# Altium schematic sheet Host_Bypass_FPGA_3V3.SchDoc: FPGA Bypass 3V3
size A4; Organization: Altium Limited.; Address1: Level 3, 12a Rodborough Rd; Address2: Frenchs Forest 2086; Address3: NSW; Address4: AUSTRALIA; DocumentNumber: 25; SheetNumber: 26; SheetTotal: 77; PageSetup: Record=PageOptions|CenterHorizontal=True|CenterVertical=True|PrintScale=0.97|XCorrection=1.00|YCorrection=1.00|PrintKind=0|BorderSize=5000000|LeftOffset=0|BottomOffset=0|Orientation=2|PaperLength=1000|PaperWidth=1000|Scale=100|PaperSource=7|PrintQuality=-4|MediaType=1|DitherType=10|PaperKind=A4 (210 x 297 mm)|PrintScaleMode=1
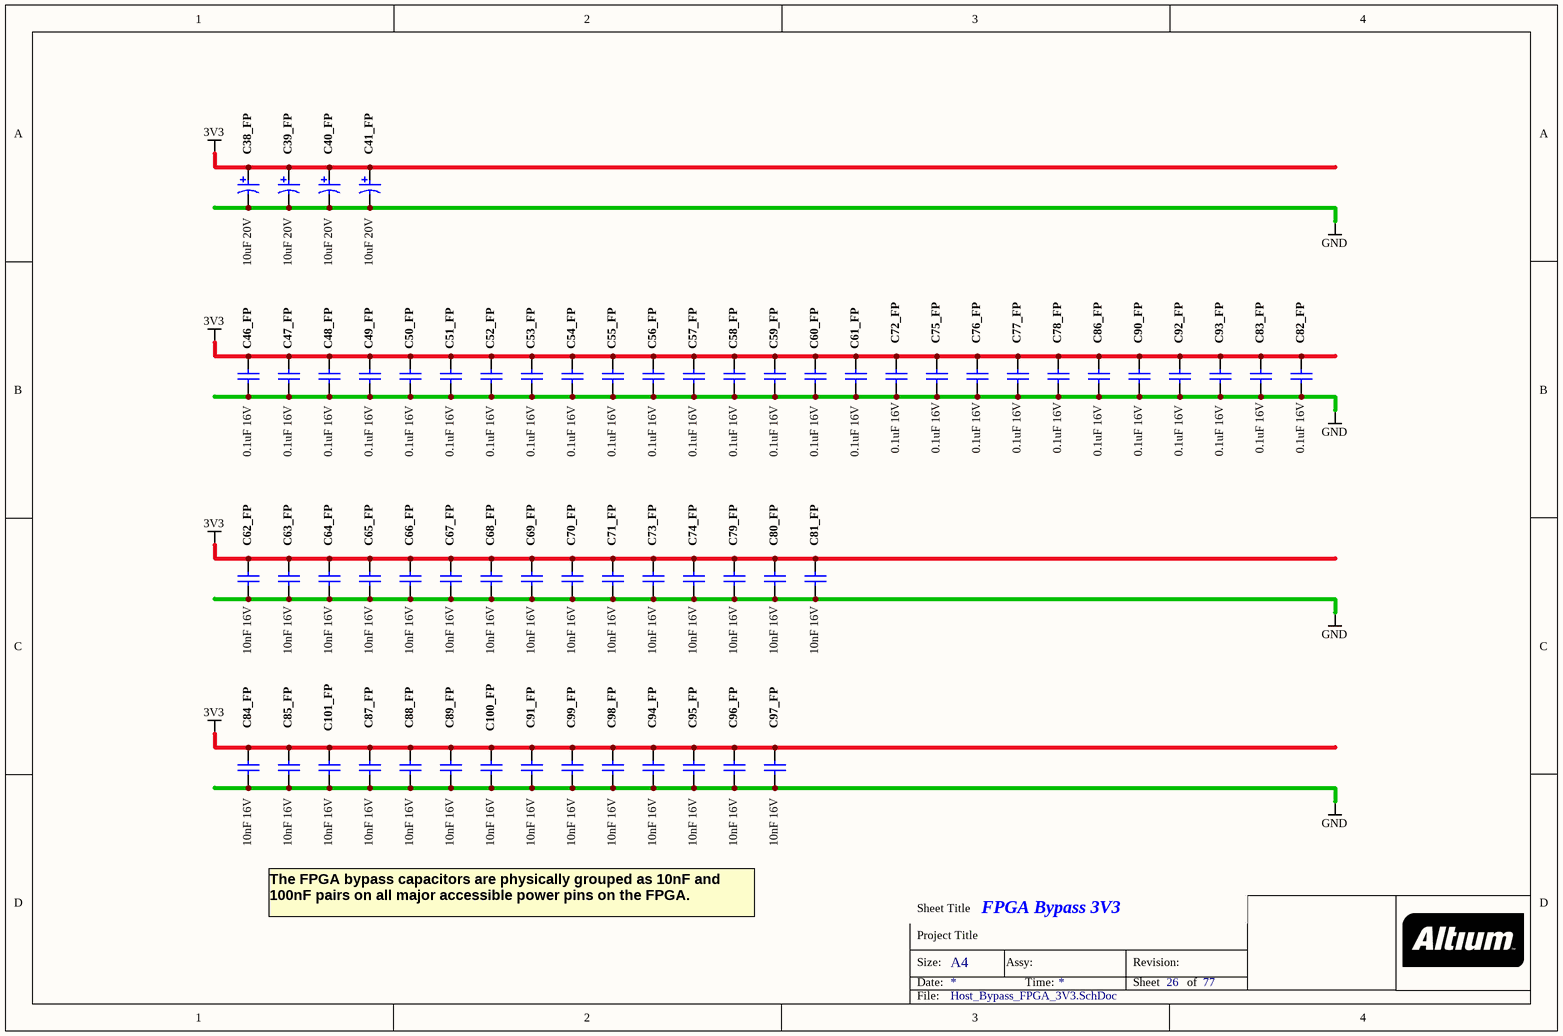
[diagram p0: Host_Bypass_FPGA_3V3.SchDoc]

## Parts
C38_FP  10uF 20V  [CAPC3528-STAR]
C39_FP  10uF 20V  [CAPC3528-STAR]
C40_FP  10uF 20V  [CAPC3528-STAR]
C41_FP  10uF 20V  [CAPC3528-STAR]
C46_FP  0.1uF 16V  [CAPC1005-STAR]
C47_FP  0.1uF 16V  [CAPC1005-STAR]
C48_FP  0.1uF 16V  [CAPC1005-STAR]
C49_FP  0.1uF 16V  [CAPC1005-STAR]
C50_FP  0.1uF 16V  [CAPC1005-STAR]
C51_FP  0.1uF 16V  [CAPC1005-STAR]
C52_FP  0.1uF 16V  [CAPC1005-STAR]
C53_FP  0.1uF 16V  [CAPC1005-STAR]
C54_FP  0.1uF 16V  [CAPC1005-STAR]
C55_FP  0.1uF 16V  [CAPC1005-STAR]
C56_FP  0.1uF 16V  [CAPC1005-STAR]
C57_FP  0.1uF 16V  [CAPC1005-STAR]
C58_FP  0.1uF 16V  [CAPC1005-STAR]
C59_FP  0.1uF 16V  [CAPC1005-STAR]
C60_FP  0.1uF 16V  [CAPC1005-STAR]
C61_FP  0.1uF 16V  [CAPC1005-STAR]
C62_FP  10nF 16V  [CAPC1005-STAR]
C63_FP  10nF 16V  [CAPC1005-STAR]
C64_FP  10nF 16V  [CAPC1005-STAR]
C65_FP  10nF 16V  [CAPC1005-STAR]
C66_FP  10nF 16V  [CAPC1005-STAR]
C67_FP  10nF 16V  [CAPC1005-STAR]
C68_FP  10nF 16V  [CAPC1005-STAR]
C69_FP  10nF 16V  [CAPC1005-STAR]
C70_FP  10nF 16V  [CAPC1005-STAR]
C71_FP  10nF 16V  [CAPC1005-STAR]
C72_FP  0.1uF 16V  [CAPC1005-STAR]
C73_FP  10nF 16V  [CAPC1005-STAR]
C74_FP  10nF 16V  [CAPC1005-STAR]
C75_FP  0.1uF 16V  [CAPC1005-STAR]
C76_FP  0.1uF 16V  [CAPC1005-STAR]
C77_FP  0.1uF 16V  [CAPC1005-STAR]
C78_FP  0.1uF 16V  [CAPC1005-STAR]
C79_FP  10nF 16V  [CAPC1005-STAR]
C80_FP  10nF 16V  [CAPC1005-STAR]
C81_FP  10nF 16V  [CAPC1005-STAR]
C82_FP  0.1uF 16V  [CAPC1005-STAR]
C83_FP  0.1uF 16V  [CAPC1005-STAR]
C84_FP  10nF 16V  [CAPC1005-STAR]
C85_FP  10nF 16V  [CAPC1005-STAR]
C86_FP  0.1uF 16V  [CAPC1005-STAR]
C87_FP  10nF 16V  [CAPC1005-STAR]
C88_FP  10nF 16V  [CAPC1005-STAR]
C89_FP  10nF 16V  [CAPC1005-STAR]
C90_FP  0.1uF 16V  [CAPC1005-STAR]
C91_FP  10nF 16V  [CAPC1005-STAR]
C92_FP  0.1uF 16V  [CAPC1005-STAR]
C93_FP  0.1uF 16V  [CAPC1005-STAR]
C94_FP  10nF 16V  [CAPC1005-STAR]
C95_FP  10nF 16V  [CAPC1005-STAR]
C96_FP  10nF 16V  [CAPC1005-STAR]
C97_FP  10nF 16V  [CAPC1005-STAR]
C98_FP  10nF 16V  [CAPC1005-STAR]
C99_FP  10nF 16V  [CAPC1005-STAR]
C100_FP  10nF 16V  [CAPC1005-STAR]
C101_FP  10nF 16V  [CAPC1005-STAR]

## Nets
3V3: C38_FP.1 C39_FP.1 C40_FP.1 C41_FP.1 C46_FP.1 C47_FP.1 C48_FP.1 C49_FP.1 C50_FP.1 C51_FP.1 C52_FP.1 C53_FP.1 C54_FP.1 C55_FP.1 C56_FP.1 C57_FP.1 C58_FP.1 C59_FP.1 C60_FP.1 C61_FP.1 C62_FP.1 C63_FP.1 C64_FP.1 C65_FP.1 C66_FP.1 C67_FP.1 C68_FP.1 C69_FP.1 C70_FP.1 C71_FP.1 C72_FP.1 C73_FP.1 C74_FP.1 C75_FP.1 C76_FP.1 C77_FP.1 C78_FP.1 C79_FP.1 C80_FP.1 C81_FP.1 C82_FP.1 C83_FP.1 C84_FP.1 C85_FP.1 C86_FP.1 C87_FP.1 C88_FP.1 C89_FP.1 C90_FP.1 C91_FP.1 C92_FP.1 C93_FP.1 C94_FP.1 C95_FP.1 C96_FP.1 C97_FP.1 C98_FP.1 C99_FP.1 C100_FP.1 C101_FP.1
GND: C38_FP.2 C39_FP.2 C40_FP.2 C41_FP.2 C46_FP.2 C47_FP.2 C48_FP.2 C49_FP.2 C50_FP.2 C51_FP.2 C52_FP.2 C53_FP.2 C54_FP.2 C55_FP.2 C56_FP.2 C57_FP.2 C58_FP.2 C59_FP.2 C60_FP.2 C61_FP.2 C62_FP.2 C63_FP.2 C64_FP.2 C65_FP.2 C66_FP.2 C67_FP.2 C68_FP.2 C69_FP.2 C70_FP.2 C71_FP.2 C72_FP.2 C73_FP.2 C74_FP.2 C75_FP.2 C76_FP.2 C77_FP.2 C78_FP.2 C79_FP.2 C80_FP.2 C81_FP.2 C82_FP.2 C83_FP.2 C84_FP.2 C85_FP.2 C86_FP.2 C87_FP.2 C88_FP.2 C89_FP.2 C90_FP.2 C91_FP.2 C92_FP.2 C93_FP.2 C94_FP.2 C95_FP.2 C96_FP.2 C97_FP.2 C98_FP.2 C99_FP.2 C100_FP.2 C101_FP.2

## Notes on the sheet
- The FPGA bypass capacitors are physically grouped as 10nF and 100nF pairs on all major accessible power pins on the FPGA.

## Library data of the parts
C38_FP C39_FP C40_FP C41_FP = D-101-0007: Capacitor, Tantalum, 10uF 10% 20V MCCT-B (3528); Polarity: Polarized
C46_FP C47_FP C48_FP C49_FP C50_FP C51_FP C52_FP C53_FP C54_FP C55_FP C56_FP C57_FP C58_FP C59_FP C60_FP C61_FP C72_FP C75_FP C76_FP C77_FP C78_FP C82_FP C83_FP C86_FP C90_FP C92_FP C93_FP = D-101-0080: Capacitor, Ceramic, 0.1uF 10% 16V 0402 (1005) X7R; Polarity: Non-Polarized
C62_FP C63_FP C64_FP C65_FP C66_FP C67_FP C68_FP C69_FP C70_FP C71_FP C73_FP C74_FP C79_FP C80_FP C81_FP C84_FP C85_FP C87_FP C88_FP C89_FP C91_FP C94_FP C95_FP C96_FP C97_FP C98_FP C99_FP C100_FP C101_FP = D-101-0077: Capacitor, Ceramic, 10nF 10% 16V 0402 (1005) X7R; Polarity: Non-Polarized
